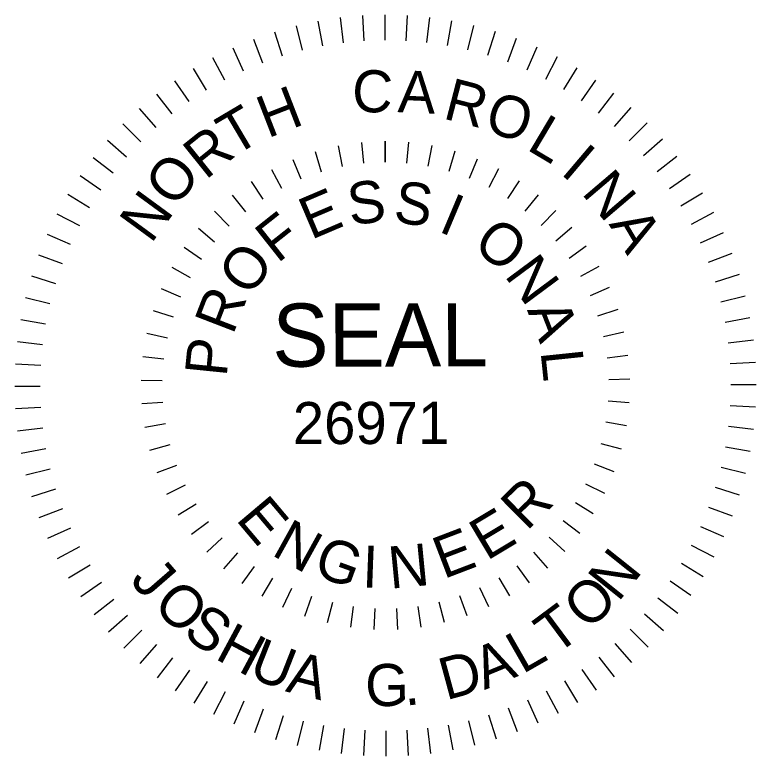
# Model space of a CAD drawing. Extents: x 2111095 to 2115970, y 670428 to 672393.
# Drawn here: x 2113181.9 to 2113253.6, y 672321.2 to 672392.9 of the extents above; entities that cross this region are included whole.
import ezdxf

# ---------------------------------------------------------------- set-up
doc = ezdxf.new("R2010")
doc.units = 0
doc.layers.add('Default', color=7, linetype='Continuous')

msp = doc.modelspace()

# ---------------------------------------------------------------- linework, layer by layer
at = {"layer": 'Default'}
for p, q in [((2113213.401, 672392.612), (2113213.699, 672390.189)), ((2113215.557, 672392.813), (2113215.708, 672390.375)), ((2113217.723, 672392.883), (2113217.727, 672390.439)), ((2113219.888, 672392.821), (2113219.747, 672390.383)), ((2113222.045, 672392.629), (2113221.756, 672390.205)), ((2113211.262, 672392.285), (2113211.705, 672389.883)), ((2113224.186, 672392.31), (2113223.751, 672389.906)), ((2113207.058, 672391.242), (2113207.79, 672388.906)), ((2113209.147, 672391.827), (2113209.732, 672389.455)), ((2113226.302, 672391.859), (2113225.726, 672389.485)), ((2113228.393, 672391.282), (2113227.671, 672388.943)), ((2113205.015, 672390.532), (2113205.887, 672388.246)), ((2113230.439, 672390.579), (2113229.575, 672388.291)), ((2113232.44, 672389.75), (2113231.445, 672387.522)), ((2113203.017, 672389.695), (2113204.021, 672387.47)), ((2113201.07, 672388.747), (2113202.21, 672386.583)), ((2113234.391, 672388.81), (2113233.259, 672386.642)), ((2113199.184, 672387.678), (2113200.455, 672385.59)), ((2113236.281, 672387.748), (2113235.017, 672385.656)), ((2113197.369, 672386.498), (2113198.761, 672384.492)), ((2113238.1, 672386.575), (2113236.716, 672384.563)), ((2113195.629, 672385.213), (2113197.138, 672383.292)), ((2113239.844, 672385.297), (2113238.344, 672383.37)), ((2113193.966, 672383.821), (2113195.59, 672381.997)), ((2113241.513, 672383.911), (2113239.896, 672382.08)), ((2113192.393, 672382.334), (2113194.124, 672380.611)), ((2113243.091, 672382.43), (2113241.368, 672380.7)), ((2113190.912, 672380.756), (2113192.743, 672379.139)), ((2113215.464, 672380.545), (2113215.665, 672378.521)), ((2113217.746, 672380.66), (2113217.749, 672378.626)), ((2113217.749, 672378.626), (2113217.746, 672380.66)), ((2113220.028, 672380.554), (2113219.835, 672378.529)), ((2113244.579, 672380.858), (2113242.754, 672379.233)), ((2113213.208, 672380.213), (2113213.6, 672378.214)), ((2113222.285, 672380.23), (2113221.9, 672378.23)), ((2113189.527, 672379.087), (2113191.453, 672377.587)), ((2113210.992, 672379.663), (2113211.577, 672377.71)), ((2113224.503, 672379.689), (2113223.926, 672377.734)), ((2113245.97, 672379.194), (2113244.049, 672377.686)), ((2113208.838, 672378.902), (2113209.609, 672377.015)), ((2113226.66, 672378.935), (2113225.896, 672377.046)), ((2113206.77, 672377.934), (2113207.718, 672376.133)), ((2113228.731, 672377.975), (2113227.791, 672376.171)), ((2113188.248, 672377.343), (2113190.26, 672375.959)), ((2113247.256, 672377.455), (2113245.249, 672376.063)), ((2113204.803, 672376.774), (2113205.922, 672375.069)), ((2113230.702, 672376.823), (2113229.59, 672375.114)), ((2113187.075, 672375.524), (2113189.168, 672374.26)), ((2113202.958, 672375.427), (2113204.239, 672373.839)), ((2113232.553, 672375.483), (2113231.279, 672373.891)), ((2113248.435, 672375.639), (2113246.347, 672374.368)), ((2113234.262, 672373.972), (2113232.841, 672372.51)), ((2113186.014, 672373.633), (2113188.182, 672372.502)), ((2113201.255, 672373.91), (2113202.681, 672372.453)), ((2113249.504, 672373.753), (2113247.34, 672372.613)), ((2113199.703, 672372.236), (2113201.26, 672370.926)), ((2113235.82, 672372.304), (2113234.268, 672370.988)), ((2113185.073, 672371.683), (2113187.302, 672370.687)), ((2113250.452, 672371.807), (2113248.227, 672370.803)), ((2113198.318, 672370.42), (2113199.996, 672369.263)), ((2113237.212, 672370.494), (2113235.538, 672369.33)), ((2113184.244, 672369.682), (2113186.533, 672368.818)), ((2113251.289, 672369.809), (2113249.003, 672368.936)), ((2113197.12, 672368.48), (2113198.899, 672367.488)), ((2113238.417, 672368.558), (2113236.642, 672367.56)), ((2113183.541, 672367.636), (2113185.88, 672366.914)), ((2113251.999, 672367.766), (2113249.663, 672367.034)), ((2113196.109, 672366.428), (2113197.979, 672365.619)), ((2113239.436, 672366.51), (2113237.569, 672365.693)), ((2113182.964, 672365.545), (2113185.338, 672364.969)), ((2113252.584, 672365.676), (2113250.212, 672365.091)), ((2113195.306, 672364.291), (2113197.246, 672363.669)), ((2113240.247, 672364.376), (2113238.31, 672363.746)), ((2113182.514, 672363.428), (2113184.918, 672362.994)), ((2113253.042, 672363.562), (2113250.64, 672363.118)), ((2113194.709, 672362.089), (2113196.699, 672361.653)), ((2113240.853, 672362.176), (2113238.864, 672361.733)), ((2113182.195, 672361.288), (2113184.619, 672360.999)), ((2113253.369, 672361.422), (2113250.947, 672361.124)), ((2113194.329, 672359.836), (2113196.349, 672359.598)), ((2113241.241, 672359.925), (2113239.221, 672359.679)), ((2113182.002, 672359.131), (2113184.441, 672358.99)), ((2113253.57, 672359.267), (2113251.132, 672359.116)), ((2113194.167, 672357.559), (2113196.202, 672357.512)), ((2113241.411, 672357.648), (2113239.377, 672357.594)), ((2113181.941, 672356.966), (2113184.384, 672356.97)), ((2113253.64, 672357.101), (2113251.197, 672357.096)), ((2113194.227, 672355.277), (2113196.256, 672355.427)), ((2113241.36, 672355.366), (2113239.33, 672355.509)), ((2113182.01, 672354.8), (2113184.448, 672354.951)), ((2113253.578, 672354.935), (2113251.14, 672355.077)), ((2113194.509, 672353.011), (2113196.513, 672353.358)), ((2113239.092, 672353.509), (2113241.102, 672353.175)), ((2113182.211, 672352.644), (2113184.634, 672352.942)), ((2113253.386, 672352.779), (2113250.962, 672353.067)), ((2113195.003, 672350.78), (2113196.965, 672351.319)), ((2113240.601, 672350.867), (2113238.636, 672351.398)), ((2113253.067, 672350.638), (2113250.663, 672351.072)), ((2113182.538, 672350.504), (2113184.941, 672350.948)), ((2113182.997, 672348.39), (2113185.369, 672348.975)), ((2113195.714, 672348.611), (2113197.616, 672349.336)), ((2113239.899, 672348.694), (2113237.994, 672349.413)), ((2113252.616, 672348.521), (2113250.242, 672349.098)), ((2113238.989, 672346.603), (2113237.164, 672347.503)), ((2113183.581, 672346.301), (2113185.917, 672347.032)), ((2113196.632, 672346.522), (2113198.452, 672347.429)), ((2113252.039, 672346.43), (2113249.701, 672347.153)), ((2113197.741, 672344.53), (2113199.471, 672345.604)), ((2113237.887, 672344.606), (2113236.153, 672345.673)), ((2113184.292, 672344.258), (2113186.577, 672345.13)), ((2113251.336, 672344.384), (2113249.048, 672345.248)), ((2113199.042, 672342.65), (2113200.66, 672343.89)), ((2113236.593, 672342.72), (2113234.97, 672343.954)), ((2113185.129, 672342.26), (2113187.353, 672343.264)), ((2113250.507, 672342.383), (2113248.279, 672343.379)), ((2113200.519, 672340.91), (2113202.006, 672342.297)), ((2113235.122, 672340.976), (2113233.63, 672342.357)), ((2113186.077, 672340.313), (2113188.24, 672341.453)), ((2113249.567, 672340.433), (2113247.399, 672341.565)), ((2113202.153, 672339.318), (2113203.503, 672340.846)), ((2113233.494, 672339.378), (2113232.138, 672340.899)), ((2113187.145, 672338.427), (2113189.233, 672339.698)), ((2113231.715, 672337.945), (2113230.515, 672339.589)), ((2113248.505, 672338.543), (2113246.413, 672339.806)), ((2113203.938, 672337.893), (2113205.131, 672339.541)), ((2113205.849, 672336.645), (2113206.88, 672338.404)), ((2113229.809, 672336.69), (2113228.771, 672338.445)), ((2113188.325, 672336.612), (2113190.332, 672338.003)), ((2113207.875, 672335.588), (2113208.73, 672337.438)), ((2113227.786, 672335.626), (2113226.925, 672337.472)), ((2113247.332, 672336.723), (2113245.32, 672338.108)), ((2113189.611, 672334.872), (2113191.531, 672336.38)), ((2113209.992, 672334.729), (2113210.665, 672336.654)), ((2113212.65, 672336.062), (2113212.164, 672334.082)), ((2113223.488, 672334.103), (2113222.995, 672336.081)), ((2113225.673, 672334.759), (2113224.992, 672336.681)), ((2113246.053, 672334.979), (2113244.127, 672336.48)), ((2113214.422, 672333.647), (2113214.711, 672335.662)), ((2113216.694, 672333.429), (2113216.786, 672335.464)), ((2113218.976, 672333.433), (2113218.876, 672335.468)), ((2113221.247, 672333.66), (2113220.951, 672335.674)), ((2113191.002, 672333.209), (2113192.827, 672334.833)), ((2113244.668, 672333.31), (2113242.838, 672334.927)), ((2113192.489, 672331.637), (2113194.213, 672333.366)), ((2113243.187, 672331.732), (2113241.457, 672333.456)), ((2113194.067, 672330.155), (2113195.684, 672331.985)), ((2113241.615, 672330.245), (2113239.99, 672332.07)), ((2113195.736, 672328.77), (2113197.237, 672330.696)), ((2113239.951, 672328.854), (2113238.443, 672330.774)), ((2113238.212, 672327.568), (2113236.82, 672329.575)), ((2113197.48, 672327.491), (2113198.865, 672329.503)), ((2113199.3, 672326.318), (2113200.563, 672328.411)), ((2113236.397, 672326.388), (2113235.125, 672328.476)), ((2113201.19, 672325.257), (2113202.322, 672327.424)), ((2113234.51, 672325.319), (2113233.37, 672327.483)), ((2113203.141, 672324.316), (2113204.136, 672326.544)), ((2113232.563, 672324.372), (2113231.56, 672326.596)), ((2113205.141, 672323.487), (2113206.005, 672325.775)), ((2113230.566, 672323.535), (2113229.693, 672325.82)), ((2113207.187, 672322.784), (2113207.91, 672325.123)), ((2113209.279, 672322.207), (2113209.854, 672324.581)), ((2113226.434, 672322.24), (2113225.848, 672324.611)), ((2113228.522, 672322.824), (2113227.791, 672325.16)), ((2113211.395, 672321.757), (2113211.829, 672324.161)), ((2113213.536, 672321.438), (2113213.824, 672323.862)), ((2113222.179, 672321.454), (2113221.881, 672323.877)), ((2113224.319, 672321.781), (2113223.875, 672324.184)), ((2113215.692, 672321.245), (2113215.834, 672323.684)), ((2113217.858, 672321.184), (2113217.853, 672323.627)), ((2113220.024, 672321.253), (2113219.873, 672323.691))]:
    msp.add_line(p, q, dxfattribs=at)

# ---------------------------------------------------------------- texts
for s, height, rotation, p in [('C', 4.069, 357.46519, (2113214.484, 672383.547)), ('A', 4.069, 357.46519, (2113218.932, 672383.475)), ('R', 4.069, 345.45588, (2113223.244, 672382.882)), ('H', 4.069, 21.17588, (2113206.391, 672380.917)), ('O', 4.069, 342.39907, (2113227.189, 672381.718)), ('T', 4.069, 30.60782, (2113203.118, 672379.138)), ('L', 4.069, 329.26278, (2113231.333, 672379.914)), ('R', 4.069, 38.76879, (2113200.386, 672376.856)), ('I', 4.069, 319.68731, (2113234.619, 672377.557)), ('O', 4.069, 51.82552, (2113197.443, 672374.109)), ('N', 4.069, 310.39285, (2113236.662, 672375.642)), ('S', 4.069, 7.75634, (2113214.404, 672372.501)), ('E', 4.069, 23.05259, (2113210.585, 672371.095)), ('S', 4.069, 352.4601, (2113218.467, 672372.846)), ('N', 4.069, 53.78495, (2113195.112, 672370.667)), ('I', 4.069, 337.16385, (2113222.795, 672371.976)), ('F', 4.069, 38.34884, (2113207.333, 672368.787)), ('A', 4.069, 300.62532, (2113239.353, 672372.643)), ('O', 4.069, 321.86761, (2113226.08, 672370.397)), ('O', 4.069, 53.64508, (2113204.633, 672365.5)), ('N', 4.069, 306.57136, (2113229.22, 672367.677)), ('R', 4.069, 68.94133, (2113203.029, 672361.842)), ('SEAL', 6.1088, 0.10822, (2113206.842, 672358.845)), ('A', 4.069, 291.27512, (2113231.458, 672364.349)), ('P', 4.069, 84.23758, (2113202.421, 672357.807)), ('L', 4.069, 275.97887, (2113232.783, 672360.323)), ('26971', 4.0691, 0.10822, (2113208.829, 672351.362)), ('R', 4.069, 44.67311, (2113231.448, 672342.877)), ('E', 4.069, 310.17831, (2113203.229, 672344.081)), ('E', 4.069, 30.90203, (2113227.576, 672340.033)), ('N', 4.069, 331.03339, (2113206.654, 672340.695)), ('E', 4.069, 20.91614, (2113223.404, 672338.288)), ('G', 4.069, 339.79962, (2113210.641, 672338.795)), ('N', 4.069, 5.52408, (2113218.252, 672337.37)), ('I', 4.069, 357.89442, (2113215.49, 672337.501)), ('N', 4.069, 51.40581, (2113240.29, 672336.005)), ('J', 4.069, 310.96734, (2113192.983, 672338.153)), ('O', 4.069, 44.00131, (2113237.423, 672333.245)), ('O', 4.069, 317.17756, (2113195.141, 672335.607)), ('T', 4.069, 36.59681, (2113234.226, 672330.877)), ('S', 4.069, 324.58206, (2113198.056, 672332.898)), ('H', 4.069, 331.74771, (2113201.186, 672330.655)), ('U', 4.069, 338.55507, (2113204.397, 672328.902)), ('L', 4.069, 29.78944, (2113231.038, 672329.081)), ('A', 4.069, 22.38494, (2113227.357, 672327.571)), ('A', 4.069, 345.84015, (2113208.037, 672327.461)), ('D', 4.069, 15.2193, (2113223.638, 672326.574)), ('G', 4.069, 0.64915, (2113215.845, 672326.008)), ('.', 4.069, 7.8148, (2113219.695, 672326.038))]:
    msp.add_text(s, height=height, rotation=rotation, dxfattribs=at).set_placement(p)

doc.saveas('drawing.dxf')
